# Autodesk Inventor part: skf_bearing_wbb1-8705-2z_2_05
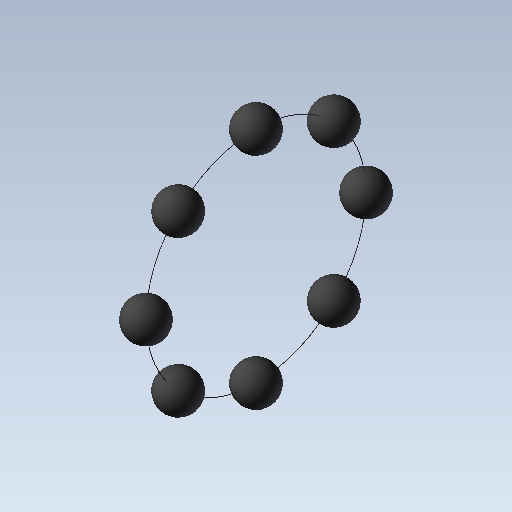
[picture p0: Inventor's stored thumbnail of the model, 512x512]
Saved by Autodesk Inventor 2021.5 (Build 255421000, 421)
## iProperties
Created: 2023-11
Part Number: skf_bearing_wbb1-8705-2z_2_05
Checked By: TraceParts S.A.
Material: Generic
Catalog Web Link: www.traceparts.com
Document SubType Name: Modeling
Designer: TraceParts
Density: 1 g/cm^3
Appearance: Default
Company: TraceParts S.A.
Author: TraceParts
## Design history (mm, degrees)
feature "skf_bearing_wbb1-8705-2z_2_05.ipt"
body "Solid1"
